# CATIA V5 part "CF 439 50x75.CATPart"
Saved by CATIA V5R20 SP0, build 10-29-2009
Part number: CF 439 50x75
Definition: NONE
Nomenclature: CF 439 50x75
Source: Unknown
Description: CF 439 50x75
Bounding box of the stored display mesh (mm): x -39.5 to 39.5, y 0 to 75, z -39.5 to 39.5
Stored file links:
  C:\Users\Utente\Desktop\IO LAVORO\3D X SITO CF\X SITO\CF 439\CF 439 50x75.CATPart
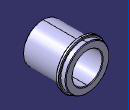
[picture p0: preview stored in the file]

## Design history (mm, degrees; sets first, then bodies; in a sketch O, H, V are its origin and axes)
Body1 "CF 439 50x75" (main body)
  Solid1: solid without history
